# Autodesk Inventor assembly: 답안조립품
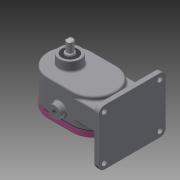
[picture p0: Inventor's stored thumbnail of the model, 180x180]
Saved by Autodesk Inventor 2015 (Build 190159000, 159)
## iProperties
Created: 2020-09
Part Number: 답안조립품
Document SubType Name: Assembly
Designer: LINEART-SSD.D4.16.07
Author: LINEART-SSD.D4.16.07
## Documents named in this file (11)
- C:\Users\LINEART-SSD.D4.16.07\Desktop\700906V1026\답안조립품.iam
- C:\Users\LINEART-SSD.D4.16.07\Desktop\700906V1026\본체.ipt
- C:\Users\LINEART-SSD.D4.16.07\Desktop\700906V1026\베어링부시.ipt
- C:\Users\LINEART-SSD.D4.16.07\Desktop\700906V1026\메인축.ipt
- C:\Users\LINEART-SSD.D4.16.07\Desktop\700906V1026\서브축.ipt
- C:\Users\LINEART-SSD.D4.16.07\Desktop\700906V1026\키 6 x 6 x 18.ipt
- C:\Users\LINEART-SSD.D4.16.07\Desktop\700906V1026\스퍼기어.ipt
- C:\Users\LINEART-SSD.D4.16.07\Desktop\700906V1026\오일 실 16 28 7.ipt
- C:\Users\LINEART-SSD.D4.16.07\Desktop\700906V1026\개스킷.ipt
- C:\Users\LINEART-SSD.D4.16.07\Desktop\700906V1026\커버.ipt
- C:\Users\LINEART-SSD.D4.16.07\Desktop\700906V1026\볼트 M5.ipt
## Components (1 placed, 1 different names)
1. 개스킷:1
